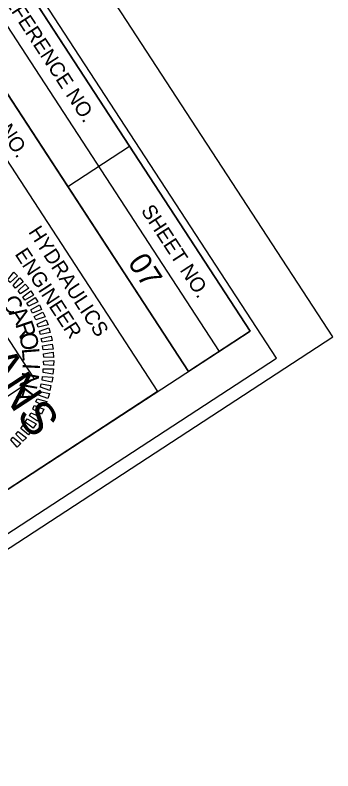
# Model space of a CAD drawing. Extents: x 1639622 to 2864602, y 842655 to 973236.
# Drawn here: x 1641350.8 to 1641458.9, y 843105.8 to 843362.5 of the extents above; entities that cross this region are included whole.
import ezdxf

# ---------------------------------------------------------------- set-up
doc = ezdxf.new("R2010")
doc.units = 0
for name, color, linetype in [('Old_Level_2', 7, 'Continuous'), ('Sheet Data Field CELL', 7, 'Continuous'), ('Sheet Plan CELL', 7, 'Continuous'), ('Sheet Plot Border Inside CELL', 7, 'Continuous'), ('Sheet Plot Border Outside CELL', 7, 'Continuous'), ('Sheet Sticker Incomplete CELL', 7, 'Continuous')]:
    doc.layers.add(name, color=color, linetype=linetype)

msp = doc.modelspace()

# ---------------------------------------------------------------- linework, layer by layer
at = {"layer": 'Old_Level_2'}
for points in [[(1641348.28, 843272.46), (1641350.39, 843275.22), (1641351.69, 843273.95), (1641349.11, 843271.7)], [(1641350.16, 843270.71), (1641352.46, 843273.28), (1641353.56, 843271.94), (1641350.99, 843269.76)], [(1641351.83, 843268.81), (1641354.28, 843271.16), (1641355.45, 843269.81), (1641352.66, 843267.86)], [(1641353.51, 843266.79), (1641356.18, 843268.91), (1641357.1, 843267.45), (1641354.17, 843265.72)], [(1641354.88, 843264.68), (1641357.69, 843266.59), (1641358.61, 843265.13), (1641355.54, 843263.61)], [(1641356.21, 843262.43), (1641359.14, 843264.16), (1641359.85, 843262.56), (1641356.74, 843261.27)], [(1641357.28, 843260.12), (1641360.31, 843261.6), (1641361.06, 843260.03), (1641357.85, 843258.99)], [(1641358.29, 843257.59), (1641361.4, 843259.06), (1641362.05, 843257.35), (1641358.69, 843256.53)], [(1641359.14, 843255.13), (1641362.26, 843256.3), (1641362.74, 843254.66), (1641359.45, 843254.01)], [(1641359.68, 843252.65), (1641363.08, 843253.5), (1641363.38, 843251.94), (1641360.05, 843251.45)], [(1641360.18, 843250.15), (1641363.47, 843250.8), (1641363.77, 843249.04), (1641360.35, 843248.87)], [(1641360.53, 843247.48), (1641363.79, 843247.98), (1641363.94, 843246.19), (1641360.57, 843246.31)], [(1641360.51, 843245), (1641364.05, 843245.19), (1641363.9, 843243.45), (1641360.63, 843243.7)], [(1641360.41, 843242.35), (1641363.88, 843242.36), (1641363.69, 843240.59), (1641360.36, 843241.11)], [(1641360.19, 843239.79), (1641363.64, 843239.54), (1641363.3, 843237.8), (1641360.09, 843238.53)], [(1641359.73, 843237.21), (1641363.02, 843236.72), (1641362.69, 843234.98), (1641359.47, 843236.09)], [(1641359.19, 843234.64), (1641362.49, 843233.97), (1641361.94, 843232.26), (1641358.74, 843233.44)], [(1641358.39, 843232.19), (1641361.64, 843231.3), (1641360.94, 843229.63), (1641357.92, 843231.12)], [(1641357.37, 843229.87), (1641360.57, 843228.69), (1641359.83, 843226.98), (1641356.92, 843228.67)], [(1641356.23, 843227.45), (1641359.39, 843226.05), (1641358.43, 843224.58), (1641355.76, 843226.37)], [(1641353.45, 843223.16), (1641356.37, 843221.29), (1641355.35, 843219.9), (1641352.84, 843222.12)], [(1641354.96, 843225.32), (1641357.99, 843223.65), (1641356.98, 843222.15), (1641354.3, 843224.24)], [(1641351.84, 843221.06), (1641354.72, 843218.97), (1641353.46, 843217.74), (1641351.14, 843220.14)], [(1641350.12, 843219.14), (1641352.79, 843216.97), (1641351.49, 843215.71), (1641349.39, 843218.26)]]:
    msp.add_lwpolyline(points, close=True, dxfattribs=at)
at = {"layer": 'Sheet Plan CELL'}
for p, q in [((1641310.9, 843415.83), (1641420.21, 843248.29)), ((1641300.41, 843408.97), (1641409.74, 843241.46)), ((1641300.41, 843408.97), (1641409.74, 843241.46)), ((1641389.67, 843317.95), (1641368.76, 843304.24))]:
    msp.add_line(p, q, dxfattribs=at)
for points in [[(1641430.74, 843255.12), (1640611, 844511.36), (1639731.66, 843937.55), (1640551.38, 842681.33)], [(1641321.42, 843422.68), (1641430.74, 843255.12), (1641409.74, 843241.46), (1641300.41, 843408.97)], [(1641344.62, 843318.36), (1641399.27, 843234.63), (1641305.06, 843173.13), (1641250.4, 843256.87)]]:
    msp.add_lwpolyline(points, close=True, dxfattribs=at)
at = {"layer": 'Sheet Plot Border Inside CELL'}
msp.add_lwpolyline([(1639645.67, 844064.72), (1640556.11, 842669.51), (1641439.64, 843246.03), (1640529.21, 844641.26)], close=True, dxfattribs=at)
at = {"layer": 'Sheet Plot Border Outside CELL'}
msp.add_lwpolyline([(1639621.82, 844064.68), (1640541.82, 842654.79), (1641458.85, 843253.19), (1640538.85, 844663.07)], close=True, dxfattribs=at)
msp.add_lwpolyline([(1639621.82, 844064.68), (1640541.82, 842654.79), (1641458.85, 843253.19), (1640538.85, 844663.07)], close=True, dxfattribs=at)
at = {"layer": 'Sheet Sticker Incomplete CELL'}
msp.add_lwpolyline([(1641257.35, 843349.17), (1641277.03, 843362.02), (1641357.36, 843238.91), (1641337.68, 843226.06)], close=True, dxfattribs=at)

# ---------------------------------------------------------------- texts
at = {"layer": 'Old_Level_2'}
for s, rotation, p in [('C', 310.3458, (1641345.96, 843264.51)), ('A', 303.1462, (1641348.54, 843261.27)), ('R', 288.747, (1641350.83, 843257.52)), ('O', 281.5471, (1641352.14, 843254.18)), ('L', 274.3468, (1641353.12, 843249.28)), ('I', 267.146, (1641353.42, 843244.37)), ('N', 259.9448, (1641353.34, 843241.6)), ('A', 252.7431, (1641352.52, 843237.31))]:
    msp.add_text(s, height=5.9, rotation=rotation, dxfattribs=at).set_placement(p)
at = {"layer": 'Sheet Data Field CELL'}
msp.add_text('07', height=7.5, rotation=303.1259, dxfattribs=at).set_placement((1641388.92, 843278.49))
at = {"layer": 'Sheet Plan CELL'}
for s, height, p in [('PROJECT REFERENCE NO.', 5.0001, (1641326.24, 843399.32)), ('R/W SHEET NO.', 5.0001, (1641323.86, 843356.22)), ('SHEET NO.', 5, (1641393.45, 843296.12)), ('HYDRAULICS', 5, (1641355.18, 843288.87)), ('ENGINEER', 5, (1641350.57, 843281.37))]:
    msp.add_text(s, height=height, rotation=303.1259, dxfattribs=at).set_placement(p)
at = {"layer": 'Sheet Sticker Incomplete CELL'}
msp.add_text('INCOMPLETE PLANS', height=11.52, rotation=303.1259, dxfattribs=at).set_placement((1641272.04, 843348.07))

doc.saveas('drawing.dxf')
